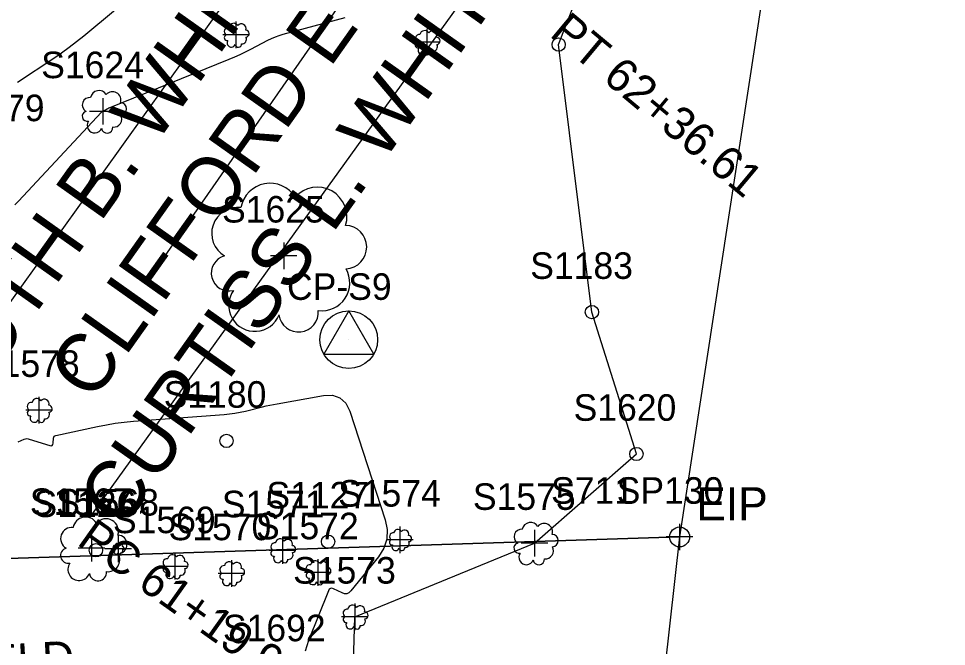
# Model space of a CAD drawing. Extents: x 816928 to 825690, y 436959 to 448212.
# Drawn here: x 819302.9 to 819442.6, y 445405.4 to 445500 of the extents above; entities that cross this region are included whole.
import ezdxf

# ---------------------------------------------------------------- set-up
doc = ezdxf.new("R2010")
doc.units = 0
for name, color, linetype in [('DESIGN - SCRATCH - User 1', 7, 'Continuous'), ('SURVEY - CENTERLINE - Preliminary Curve Text', 7, 'Continuous'), ('SURVEY - CONTOURS - Intermediate with optional Text', 7, 'Continuous'), ('SURVEY - CONTROL with Text', 7, 'Continuous'), ('SURVEY - DTM - Spot Points - Locators', 7, 'Continuous'), ('SURVEY - DTM - Spot Points - Point Numbers', 7, 'Continuous'), ('SURVEY - NON-TRANSPORTATION - Features - Points - Numbers', 7, 'Continuous'), ('SURVEY - NON-TRANSPORTATION - Features Text', 7, 'Continuous'), ('SURVEY - PROPERTY - Owners', 7, 'Continuous'), ('SURVEY - PROPERTY - Parcels', 7, 'Continuous'), ('SURVEY - PROPERTY - Property Lines', 7, 'Continuous'), ('SURVEY - PROPERTY - Property Lines - Points - Locators', 7, 'Continuous'), ('SURVEY - PROPERTY - Property Lines - Points - Numbers', 7, 'Continuous'), ('SURVEY - PROPERTY - Property Markers - Points - Locators', 7, 'Continuous'), ('SURVEY - PROPERTY - Property Markers - Points - Numbers', 7, 'Continuous'), ('SURVEY - PROPERTY - Property Markers with Text', 7, 'Continuous'), ('SURVEY - VEGETATION - Features - Points - Locators', 7, 'Continuous'), ('SURVEY - VEGETATION - Features - Points - Numbers', 7, 'Continuous'), ('SURVEY - VEGETATION - Features with Text', 7, 'Continuous')]:
    doc.layers.add(name, color=color, linetype=linetype)

msp = doc.modelspace()

# ---------------------------------------------------------------- linework, layer by layer
at = {"layer": 'DESIGN - SCRATCH - User 1'}
msp.add_lwpolyline([(819208.36, 445159.93), (819225.33, 445187.21), (819232.03, 445225.73), (819255.26, 445264.8), (819317.2, 445227.34), (819339.48, 445265.05), (819329.85, 445327.66), (819351.56, 445342.87), (819353.52, 445409.89), (819380.58, 445421), (819395.92, 445434.42), (819389.22, 445455.8), (819384.21, 445496.1), (819404.55, 445548.39), (819444.23, 445586.27), (819474.51, 445625.22), (819497, 445667.52), (819511.63, 445716.67), (819447.28, 445731.71), (819389.73, 445754.86), (819348.83, 445782.03), (819320.04, 445802.59), (819264.2, 445828.45)], dxfattribs=at)
at = {"layer": 'SURVEY - CONTOURS - Intermediate with optional Text'}
for points in [[(819302.71, 445490.44), (819308.21, 445494.07), (819309.38, 445494.86), (819310.52, 445495.69), (819311.64, 445496.55), (819312.74, 445497.43), (819317.49, 445501.4)], [(819302.31, 445471.95), (819302.9, 445472.51), (819315.4, 445485.94), (819315.42, 445485.96), (819315.43, 445485.97), (819315.45, 445485.99), (819315.48, 445486), (819315.57, 445486.07), (819315.57, 445486.07), (819315.58, 445486.07), (819315.58, 445486.07), (819315.59, 445486.08), (819315.6, 445486.09), (819315.6, 445486.09), (819315.6, 445486.09), (819315.61, 445486.09), (819315.61, 445486.09), (819316.22, 445486.42), (819316.36, 445486.49), (819316.49, 445486.55), (819316.63, 445486.61), (819316.77, 445486.67), (819334.62, 445493.92), (819335.44, 445494.27), (819336.25, 445494.63), (819337.06, 445495.01), (819337.85, 445495.42), (819340.43, 445496.76), (819340.99, 445497.03), (819341.57, 445497.27), (819342.15, 445497.48), (819342.75, 445497.66), (819352.05, 445500.19)], [(819302.84, 445436.26), (819303.73, 445436.64), (819303.93, 445436.7), (819304.12, 445436.73), (819304.32, 445436.72), (819304.51, 445436.67), (819307.59, 445435.7), (819307.8, 445435.67), (819307.95, 445435.71), (819308.04, 445435.83), (819308.09, 445436.03), (819308.16, 445436.81), (819308.19, 445436.96), (819308.26, 445437.08), (819308.37, 445437.16), (819308.51, 445437.22), (819314.76, 445438.57), (819316.11, 445438.83), (819317.46, 445439.05), (819318.81, 445439.23), (819320.18, 445439.35), (819333.86, 445440.38), (819334.66, 445440.46), (819335.46, 445440.57), (819336.26, 445440.72), (819337.05, 445440.89), (819339.62, 445441.52), (819340.17, 445441.65), (819340.72, 445441.77), (819341.28, 445441.89), (819341.84, 445441.99), (819348.81, 445443.22), (819350.18, 445443.27), (819351.29, 445442.89), (819352.15, 445442.09), (819352.75, 445440.86), (819358.09, 445424.52), (819358.4, 445423.02), (819358.34, 445421.6), (819357.9, 445420.24), (819357.08, 445418.95), (819352.93, 445413.78), (819352.64, 445413.5), (819352.32, 445413.36), (819351.98, 445413.35), (819351.6, 445413.48), (819350.31, 445414.11), (819350.06, 445414.19), (819349.84, 445414.17), (819349.67, 445414.04), (819349.54, 445413.81), (819346.53, 445406.3), (819346.03, 445404.69)]]:
    msp.add_lwpolyline(points, dxfattribs=at)
at = {"layer": 'SURVEY - CONTROL with Text'}
for p, q in [((819352.61, 445455.99), (819348.85, 445449.47)), ((819356.38, 445449.47), (819352.61, 445455.99)), ((819352.61, 445451.64), (819352.61, 445451.64)), ((819348.85, 445449.47), (819356.38, 445449.47))]:
    msp.add_line(p, q, dxfattribs=at)
msp.add_circle((819352.61, 445451.64), 4.35, dxfattribs=at)
at = {"layer": 'SURVEY - DTM - Spot Points - Locators'}
for centre in [(819384.21, 445496.1), (819389.22, 445455.8), (819334.2, 445436.39), (819395.92, 445434.42), (819349.5, 445421.21), (819314.54, 445419.92)]:
    msp.add_circle(centre, 1, dxfattribs=at)
at = {"layer": 'SURVEY - PROPERTY - Owners'}
for p, q in [((819289.26, 445440.01), (819386.81, 445576.37)), ((819313.64, 445424.86), (819420.6, 445573.61)), ((819388.11, 445555.31), (819322.07, 445460.17))]:
    msp.add_line(p, q, dxfattribs=at)
at = {"layer": 'SURVEY - PROPERTY - Parcels'}
for p, q in [((819426.04, 445576.35), (819402.42, 445421.92)), ((819402.42, 445421.92), (819168.54, 445414.43)), ((819168.54, 445414.43), (819402.42, 445421.92)), ((819402.42, 445421.92), (819380.28, 445227.76))]:
    msp.add_line(p, q, dxfattribs=at)
at = {"layer": 'SURVEY - PROPERTY - Property Lines'}
for p, q in [((819426.04, 445576.35), (819402.42, 445421.92)), ((819402.42, 445421.92), (819168.54, 445414.43)), ((819402.42, 445421.92), (819380.28, 445227.76))]:
    msp.add_line(p, q, dxfattribs=at)
at = {"layer": 'SURVEY - PROPERTY - Property Lines - Points - Locators'}
for p, q in [((819402.42, 445423.92), (819402.42, 445419.92)), ((819404.42, 445421.92), (819400.42, 445421.92))]:
    msp.add_line(p, q, dxfattribs=at)
at = {"layer": 'SURVEY - PROPERTY - Property Markers - Points - Locators'}
for p, q in [((819402.42, 445423.92), (819402.42, 445419.92)), ((819404.42, 445421.92), (819400.42, 445421.92))]:
    msp.add_line(p, q, dxfattribs=at)
at = {"layer": 'SURVEY - PROPERTY - Property Markers with Text'}
msp.add_circle((819402.42, 445421.92), 1.5, dxfattribs=at)
at = {"layer": 'SURVEY - VEGETATION - Features - Points - Locators'}
for p, q in [((819335.63, 445499.56), (819335.63, 445495.56)), ((819364.38, 445498.46), (819364.38, 445494.46)), ((819337.63, 445497.56), (819333.63, 445497.56)), ((819366.38, 445496.46), (819362.38, 445496.46)), ((819315.59, 445488.04), (819315.59, 445484.04)), ((819317.59, 445486.04), (819313.59, 445486.04)), ((819342.81, 445466.29), (819342.81, 445462.29)), ((819344.81, 445464.29), (819340.81, 445464.29)), ((819305.97, 445443.03), (819305.97, 445439.03)), ((819307.97, 445441.03), (819303.97, 445441.03)), ((819360.29, 445423.49), (819360.29, 445419.49)), ((819380.58, 445423), (819380.58, 445419)), ((819313.88, 445422.23), (819313.88, 445418.23)), ((819317.9, 445422.14), (819317.9, 445418.14)), ((819342.63, 445421.88), (819342.63, 445417.88)), ((819362.29, 445421.49), (819358.29, 445421.49)), ((819315.88, 445420.23), (819311.88, 445420.23)), ((819319.9, 445420.14), (819315.9, 445420.14)), ((819382.58, 445421), (819378.58, 445421)), ((819326.41, 445419.49), (819326.41, 445415.49)), ((819344.63, 445419.88), (819340.63, 445419.88)), ((819347.93, 445418.57), (819347.93, 445414.57)), ((819328.41, 445417.49), (819324.41, 445417.49)), ((819334.94, 445418.43), (819334.94, 445414.43)), ((819336.94, 445416.43), (819332.94, 445416.43)), ((819349.93, 445416.57), (819345.93, 445416.57)), ((819353.52, 445411.89), (819353.52, 445407.89)), ((819355.52, 445409.89), (819351.52, 445409.89))]:
    msp.add_line(p, q, dxfattribs=at)
at = {"layer": 'SURVEY - VEGETATION - Features with Text'}
for centre, radius in [((819335.65, 445497.57), 0.022), ((819364.4, 445496.46), 0.022), ((819315.64, 445486.06), 0.0391), ((819343, 445464.36), 0.137), ((819305.99, 445441.03), 0.022), ((819360.31, 445421.5), 0.0196), ((819313.95, 445420.26), 0.0587), ((819317.91, 445420.14), 0.00978), ((819342.65, 445419.89), 0.022), ((819380.64, 445421.02), 0.0391), ((819326.42, 445417.49), 0.022), ((819334.96, 445416.44), 0.022), ((819347.94, 445416.58), 0.022), ((819353.54, 445409.9), 0.022)]:
    msp.add_circle(centre, radius, dxfattribs=at)
for centre, radius, start, end in [((819334.5, 445498.1), 0.631, 82.9155, 239.7044), ((819335.29, 445498.59), 0.719, 31.9683, 169.4925), ((819336.43, 445498.5), 0.714, 342.8641, 138.7026), ((819337.1, 445497.76), 0.527, 273.117, 88.1173), ((819364.04, 445497.49), 0.719, 31.9683, 169.4925), ((819334.3, 445497.13), 0.433, 105.0317, 283.7773), ((819336.54, 445496.9), 0.679, 262.9581, 29.8037), ((819363.25, 445496.99), 0.631, 82.9155, 239.7044), ((819365.18, 445497.4), 0.714, 342.8641, 138.7026), ((819365.85, 445496.66), 0.527, 273.117, 88.1173), ((819334.92, 445496.35), 0.629, 145.0523, 338.472), ((819335.98, 445496.19), 0.479, 187.671, 4.9902), ((819363.05, 445496.03), 0.433, 105.0317, 283.7773), ((819363.67, 445495.25), 0.629, 145.0523, 338.472), ((819365.29, 445495.8), 0.679, 262.9581, 29.8037), ((819364.73, 445495.08), 0.479, 187.671, 4.9902), ((819315, 445487.89), 1.28, 31.9683, 169.4925), ((819317.04, 445487.73), 1.27, 342.8641, 138.7026), ((819313.61, 445487.01), 1.12, 82.9155, 239.7044), ((819318.22, 445486.42), 0.936, 273.117, 88.1173), ((819313.25, 445485.3), 0.77, 105.0317, 283.7773), ((819314.35, 445483.91), 1.12, 145.0523, 338.472), ((819317.23, 445484.88), 1.21, 262.9581, 29.8037), ((819316.23, 445483.61), 0.852, 187.671, 4.9902), ((819340.76, 445470.74), 4.47, 31.9683, 169.4925), ((819347.89, 445470.17), 4.44, 342.8641, 138.7026), ((819335.89, 445467.66), 3.92, 82.9155, 239.7044), ((819352.03, 445465.59), 3.28, 273.117, 88.1173), ((819334.6, 445461.67), 2.69, 105.0317, 283.7773), ((819348.54, 445460.22), 4.22, 262.9581, 29.8037), ((819338.46, 445456.81), 3.92, 145.0523, 338.472), ((819345.05, 445455.77), 2.98, 187.671, 4.9902), ((819305.63, 445442.06), 0.719, 31.9683, 169.4925), ((819306.77, 445441.97), 0.714, 342.8641, 138.7026), ((819304.64, 445440.6), 0.433, 105.0317, 283.7773), ((819304.84, 445441.57), 0.631, 82.9155, 239.7044), ((819307.44, 445441.23), 0.527, 273.117, 88.1173), ((819305.26, 445439.82), 0.629, 145.0523, 338.472), ((819306.32, 445439.65), 0.479, 187.671, 4.9902), ((819306.88, 445440.37), 0.679, 262.9581, 29.8037), ((819312.99, 445423), 1.92, 31.9683, 169.4925), ((819316.05, 445422.76), 1.9, 342.8641, 138.7026), ((819380, 445422.84), 1.28, 31.9683, 169.4925), ((819310.91, 445421.68), 1.68, 82.9155, 239.7044), ((819359.99, 445422.41), 0.639, 31.9683, 169.4925), ((819361.01, 445422.33), 0.635, 342.8641, 138.7026), ((819378.61, 445421.96), 1.12, 82.9155, 239.7044), ((819382.03, 445422.68), 1.27, 342.8641, 138.7026), ((819317.82, 445420.79), 1.4, 273.117, 88.1173), ((819342.29, 445420.91), 0.719, 31.9683, 169.4925), ((819343.43, 445420.82), 0.714, 342.8641, 138.7026), ((819359.11, 445421.12), 0.385, 105.0317, 283.7773), ((819359.3, 445421.97), 0.561, 82.9155, 239.7044), ((819361.6, 445421.68), 0.468, 273.117, 88.1173), ((819383.22, 445421.37), 0.936, 273.117, 88.1173), ((819310.36, 445419.11), 1.15, 105.0317, 283.7773), ((819317.4, 445420.38), 0.28, 82.9155, 239.7044), ((819317.31, 445419.95), 0.192, 105.0317, 283.7773), ((819317.75, 445420.6), 0.319, 31.9683, 169.4925), ((819318.26, 445420.56), 0.317, 342.8641, 138.7026), ((819318.31, 445419.85), 0.302, 262.9581, 29.8037), ((819318.55, 445420.23), 0.234, 273.117, 88.1173), ((819341.5, 445420.42), 0.631, 82.9155, 239.7044), ((819344.1, 445420.08), 0.527, 273.117, 88.1173), ((819359.67, 445420.42), 0.56, 145.0523, 338.472), ((819360.61, 445420.28), 0.426, 187.671, 4.9902), ((819361.11, 445420.91), 0.603, 262.9581, 29.8037), ((819378.24, 445420.25), 0.77, 105.0317, 283.7773), ((819382.22, 445419.84), 1.21, 262.9581, 29.8037), ((819316.33, 445418.49), 1.81, 262.9581, 29.8037), ((819317.59, 445419.6), 0.28, 145.0523, 338.472), ((819318.06, 445419.53), 0.213, 187.671, 4.9902), ((819325.28, 445418.02), 0.631, 82.9155, 239.7044), ((819326.06, 445418.52), 0.719, 31.9683, 169.4925), ((819327.21, 445418.43), 0.714, 342.8641, 138.7026), ((819341.3, 445419.45), 0.433, 105.0317, 283.7773), ((819341.92, 445418.67), 0.629, 145.0523, 338.472), ((819342.98, 445418.51), 0.479, 187.671, 4.9902), ((819343.54, 445419.22), 0.679, 262.9581, 29.8037), ((819379.34, 445418.86), 1.12, 145.0523, 338.472), ((819381.22, 445418.57), 0.852, 187.671, 4.9902), ((819312.01, 445417.03), 1.68, 145.0523, 338.472), ((819325.08, 445417.06), 0.433, 105.0317, 283.7773), ((819327.32, 445416.83), 0.679, 262.9581, 29.8037), ((819327.88, 445417.69), 0.527, 273.117, 88.1173), ((819333.82, 445416.97), 0.631, 82.9155, 239.7044), ((819334.6, 445417.46), 0.719, 31.9683, 169.4925), ((819335.75, 445417.37), 0.714, 342.8641, 138.7026), ((819336.41, 445416.63), 0.527, 273.117, 88.1173), ((819346.8, 445417.11), 0.631, 82.9155, 239.7044), ((819347.58, 445417.6), 0.719, 31.9683, 169.4925), ((819348.73, 445417.51), 0.714, 342.8641, 138.7026), ((819349.4, 445416.78), 0.527, 273.117, 88.1173), ((819314.84, 445416.58), 1.28, 187.671, 4.9902), ((819325.7, 445416.28), 0.629, 145.0523, 338.472), ((819326.76, 445416.11), 0.479, 187.671, 4.9902), ((819333.61, 445416), 0.433, 105.0317, 283.7773), ((819335.85, 445415.77), 0.679, 262.9581, 29.8037), ((819346.6, 445416.15), 0.433, 105.0317, 283.7773), ((819347.21, 445415.37), 0.629, 145.0523, 338.472), ((819348.84, 445415.91), 0.679, 262.9581, 29.8037), ((819334.23, 445415.22), 0.629, 145.0523, 338.472), ((819335.29, 445415.05), 0.479, 187.671, 4.9902), ((819348.27, 445415.2), 0.479, 187.671, 4.9902), ((819353.18, 445410.93), 0.719, 31.9683, 169.4925), ((819354.32, 445410.83), 0.714, 342.8641, 138.7026), ((819352.39, 445410.43), 0.631, 82.9155, 239.7044), ((819354.99, 445410.1), 0.527, 273.117, 88.1173), ((819352.19, 445409.47), 0.433, 105.0317, 283.7773), ((819352.81, 445408.69), 0.629, 145.0523, 338.472), ((819354.43, 445409.23), 0.679, 262.9581, 29.8037), ((819353.87, 445408.52), 0.479, 187.671, 4.9902)]:
    msp.add_arc(centre, radius, start, end, dxfattribs=at)

# ---------------------------------------------------------------- texts
at = {"layer": 'SURVEY - CENTERLINE - Preliminary Curve Text'}
for s, rotation, p in [('PT 62+36.61', 320.1417, (819382.68, 445497.46)), ('PC 61+19.94', 324.5985, (819311.52, 445420.87))]:
    msp.add_text(s, height=5, rotation=rotation, dxfattribs=at).set_placement(p)
at = {"layer": 'SURVEY - CONTROL with Text'}
msp.add_text('CP-S9', height=4, dxfattribs=at).set_placement((819343.31, 445457.64))
at = {"layer": 'SURVEY - DTM - Spot Points - Point Numbers'}
for s, p in [('S1179', (819291.34, 445484.56)), ('S1183', (819379.93, 445460.8)), ('S1180', (819324.74, 445441.39)), ('S1620', (819386.46, 445439.42)), ('S1127', (819340.21, 445426.21)), ('S1126', (819305.14, 445424.92))]:
    msp.add_text(s, height=4, dxfattribs=at).set_placement(p)
at = {"layer": 'SURVEY - NON-TRANSPORTATION - Features - Points - Numbers'}
msp.add_text('S1692', height=4, dxfattribs=at).set_placement((819333.66, 445406.2))
at = {"layer": 'SURVEY - NON-TRANSPORTATION - Features Text'}
msp.add_text('FIELD', height=5, rotation=3.3388, dxfattribs=at).set_placement((819292.5, 445400.23))
at = {"layer": 'SURVEY - PROPERTY - Owners'}
for s, p in [('RUTH B. WHITE ETVIR ', (819294.49, 445439.98)), ('CURTISS L. WHITE ETUX', (819318.56, 445422.93)), ('    CLIFFORD ETAL ', (819306.53, 445431.45))]:
    msp.add_text(s, height=8.75, rotation=54.6815, dxfattribs=at).set_placement(p)
at = {"layer": 'SURVEY - PROPERTY - Property Lines - Points - Numbers'}
msp.add_text('SP130', height=4, dxfattribs=at).set_placement((819392.95, 445426.92))
at = {"layer": 'SURVEY - PROPERTY - Property Markers - Points - Numbers'}
msp.add_text('S711', height=4, dxfattribs=at).set_placement((819383.06, 445426.92))
at = {"layer": 'SURVEY - PROPERTY - Property Markers with Text'}
msp.add_text('EIP', height=5, dxfattribs=at).set_placement((819404.92, 445424.42))
at = {"layer": 'SURVEY - VEGETATION - Features - Points - Numbers'}
for s, p in [('S1624', (819306.3, 445491.04)), ('S1625', (819333.53, 445469.29)), ('S1578', (819296.63, 445446.03)), ('S1574', (819351, 445426.49)), ('S1575', (819371.3, 445426)), ('S1567', (819304.59, 445425.23)), ('S1568', (819308.56, 445425.14)), ('S1571', (819333.5, 445424.88)), ('S1569', (819317.1, 445422.49)), ('S1570', (819325.48, 445421.43)), ('S1572', (819338.64, 445421.57)), ('S1573', (819344.23, 445414.89))]:
    msp.add_text(s, height=4, dxfattribs=at).set_placement(p)

doc.saveas('drawing.dxf')
